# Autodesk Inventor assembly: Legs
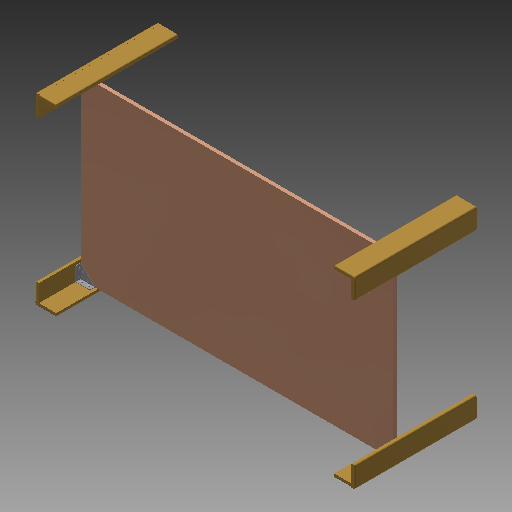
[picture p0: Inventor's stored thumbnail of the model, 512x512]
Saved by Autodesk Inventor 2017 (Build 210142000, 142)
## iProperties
Created: 2017-05
Part Number: Legs
Document SubType Name: Assembly
Designer: John
Author: John
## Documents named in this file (3)
- D:\3D Printer Designs\John Ledden Designs\Infinity Mirror Table\SavanDrawings\Legs.iam
- D:\3D Printer Designs\John Ledden Designs\Infinity Mirror Table\SavanDrawings\Shelf.ipt
- D:\3D Printer Designs\John Ledden Designs\Infinity Mirror Table\SavanDrawings\LegAssm1.iam
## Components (5 placed, 5 different names)
1. Shelf_1017
2. LegAssm1_1018 [sub-assembly]
3. LegAssm1_1019 [sub-assembly]
4. LegAssm1_1020 [sub-assembly]
5. LegAssm1_1021 [sub-assembly]
